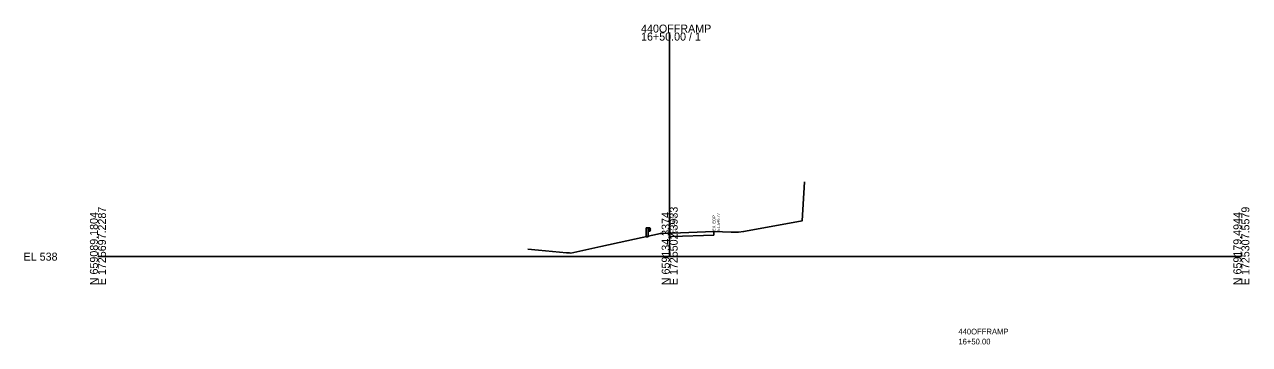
# Model space of a CAD drawing. Extents: x 1728898 to 1729326, y 661368 to 668397.
# Drawn here: x 1728897.8 to 1729326.3, y 663347.3 to 663459.4 of the extents above; entities that cross this region are included whole.
import ezdxf

# ---------------------------------------------------------------- set-up
doc = ezdxf.new("R2010")
doc.units = 0
for name, color, linetype in [('DESIGN - SHEET - Light Grid', 7, 'Continuous'), ('DESIGN - TYPICAL - Guardrail', 7, 'Continuous'), ('DESIGN - TYPICAL - Warning Text', 7, 'Continuous'), ('SURVEY - GROUND - Existing Pavement Layer', 7, 'Continuous'), ('SURVEY - GROUND - Existing Pavement Text', 7, 'Continuous'), ('SURVEY - GROUND - Top of Ground', 7, 'Continuous')]:
    doc.layers.add(name, color=color, linetype=linetype)

msp = doc.modelspace()

# ---------------------------------------------------------------- linework, layer by layer
at = {"layer": 'DESIGN - SHEET - Light Grid'}
for p, q in [((1729123.44, 663378.11), (1729123.44, 663456.57)), ((1728923.44, 663378.11), (1729123.44, 663378.11)), ((1729123.44, 663378.11), (1729323.44, 663378.11))]:
    msp.add_line(p, q, dxfattribs=at)
at = {"layer": 'DESIGN - TYPICAL - Guardrail'}
for p, q in [((1729115.26, 663388.15), (1729115.26, 663385.5)), ((1729115.93, 663388.15), (1729115.26, 663388.15)), ((1729115.93, 663388.15), (1729116.55, 663388.15)), ((1729115.93, 663385.5), (1729115.93, 663388.15)), ((1729116.55, 663386.99), (1729115.93, 663386.99)), ((1729116.55, 663388.15), (1729116.55, 663386.99)), ((1729116.55, 663388.08), (1729116.64, 663388.03)), ((1729116.59, 663387.67), (1729116.55, 663387.61)), ((1729116.55, 663387.61), (1729116.55, 663387.57)), ((1729116.55, 663387.57), (1729116.55, 663387.53)), ((1729116.55, 663387.53), (1729116.59, 663387.47)), ((1729116.64, 663387.11), (1729116.55, 663387.06)), ((1729116.79, 663387.79), (1729116.59, 663387.67)), ((1729116.59, 663387.47), (1729116.79, 663387.35)), ((1729116.64, 663388.03), (1729116.79, 663387.91)), ((1729116.79, 663387.24), (1729116.64, 663387.11)), ((1729116.79, 663387.91), (1729116.83, 663387.85)), ((1729116.83, 663387.85), (1729116.79, 663387.79)), ((1729116.79, 663387.35), (1729116.83, 663387.3)), ((1729116.83, 663387.3), (1729116.79, 663387.24)), ((1729115.26, 663384.94), (1729115.26, 663385.5)), ((1729115.51, 663385.04), (1729115.26, 663384.94)), ((1729115.76, 663385), (1729115.51, 663385.04)), ((1729115.93, 663385.04), (1729115.76, 663385)), ((1729115.93, 663385.5), (1729115.93, 663385.04))]:
    msp.add_line(p, q, dxfattribs=at)
at = {"layer": 'SURVEY - GROUND - Existing Pavement Layer'}
for p, q in [((1729123.42, 663385.07), (1729123.42, 663386.32)), ((1729124.33, 663385.11), (1729138.95, 663385.63)), ((1729138.95, 663386.88), (1729138.95, 663385.63)), ((1729123.42, 663385.07), (1729124.33, 663385.11))]:
    msp.add_line(p, q, dxfattribs=at)
at = {"layer": 'SURVEY - GROUND - Top of Ground'}
msp.add_lwpolyline([(1729073.79, 663380.72), (1729077.6, 663380.38), (1729087.37, 663379.49), (1729088.43, 663379.39), (1729088.85, 663379.35), (1729099.31, 663381.65), (1729120.19, 663386.22), (1729120.68, 663386.23), (1729122.63, 663386.3), (1729123.42, 663386.32), (1729124.33, 663386.36), (1729138.95, 663386.88), (1729144.92, 663386.71), (1729147.48, 663386.63), (1729149.31, 663386.91), (1729152.59, 663387.51), (1729169.85, 663390.68), (1729170.66, 663404.26)], dxfattribs=at)

# ---------------------------------------------------------------- texts
at = {"layer": 'DESIGN - SHEET - Light Grid'}
for s, p in [('440OFFRAMP', (1729113.44, 663456.57)), ('16+50.00 / 1', (1729113.44, 663453.77)), ('EL 538', (1728897.44, 663376.71))]:
    msp.add_text(s, height=2.8, dxfattribs=at).set_placement(p)
for s, p in [('E 1725697.2287', (1728926.24, 663368.11)), ('E 1725502.3933', (1729126.24, 663368.11)), ('E 1725307.5579', (1729326.24, 663368.11)), ('N 659089.1804', (1728923.44, 663368.11)), ('N 659134.3374', (1729123.44, 663368.11)), ('N 659179.4944', (1729323.44, 663368.11))]:
    msp.add_text(s, height=2.8, rotation=90, dxfattribs=at).set_placement(p)
at = {"layer": 'DESIGN - TYPICAL - Warning Text'}
for s, p in [('440OFFRAMP', (1729224.44, 663350.86)), ('16+50.00', (1729224.44, 663347.36))]:
    msp.add_text(s, height=2, dxfattribs=at).set_placement(p)
at = {"layer": 'SURVEY - GROUND - Existing Pavement Text'}
for s, p in [('EX. EOP', (1729123.92, 663386.52)), ('EL.546.22', (1729125.42, 663386.52)), ('EX. EOP', (1729139.45, 663387.08)), ('EL.546.77', (1729140.95, 663387.08))]:
    msp.add_text(s, height=1, rotation=90, dxfattribs=at).set_placement(p)

doc.saveas('drawing.dxf')
